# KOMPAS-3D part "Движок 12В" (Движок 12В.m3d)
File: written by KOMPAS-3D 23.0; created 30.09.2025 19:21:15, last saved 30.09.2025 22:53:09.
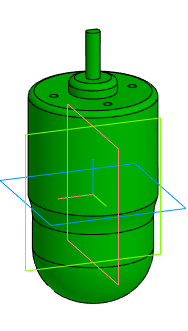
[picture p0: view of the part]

Document properties: Автор: Inspektor_Kot; Полное имя файла: C:\Users\Lost\Desktop\Варианты\Вариант 6 +\Движок 12В.m3d

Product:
- Part/product: Движок 12В
    Масса: 0.839217

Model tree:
1. Операция без истории:1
